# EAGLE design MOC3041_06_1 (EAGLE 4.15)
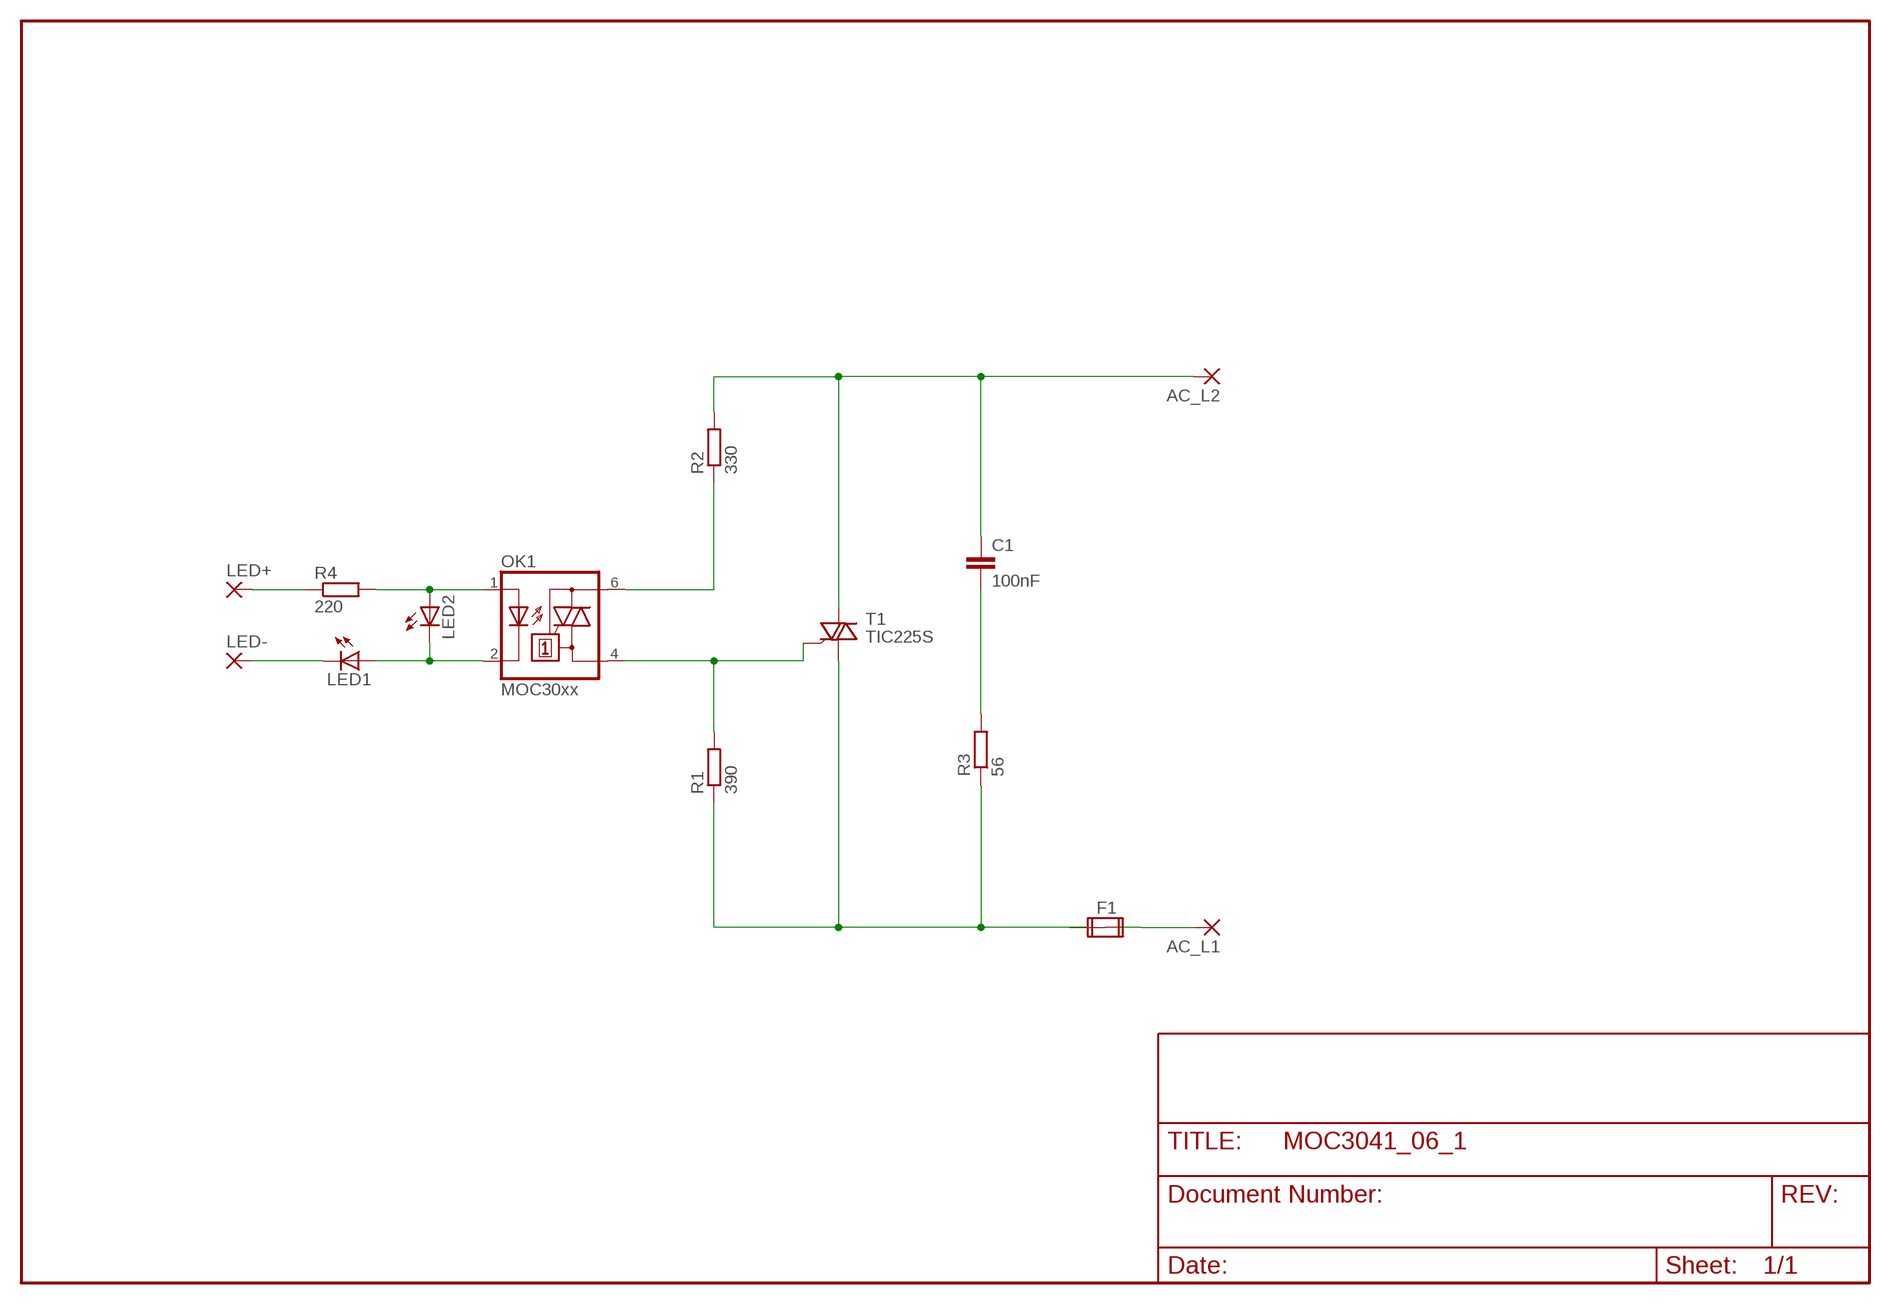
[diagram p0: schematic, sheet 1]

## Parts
AC_L1  3,17/1,1  [3,17/1,1]
AC_L2  3,17/1,1  [3,17/1,1]
C1  100nF  C-EU150-072X183  [C150-072X183]
F1  FUSE2P  [FUSE1]
LED1  LED3MM  [LED3MM]
LED2  LED3MM  [LED3MM]
LED+  3,17/1,1  [3,17/1,1]
LED-  3,17/1,1  [3,17/1,1]
OK1  MOC30xx  IL410  [DIL06]
R1  390  R-EU_0207/7  [0207/7]
R2  330  R-EU_0207/7  [0207/7]
R3  56  R-EU_0207/7  [0207/7]
R4  220  R-EU_0207/7  [0207/7]
T1  TIC225S  [TO220DS]

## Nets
N$1: AC_L2.1(P) C1.1 R2.2 T1.A2
N$2: C1.2 R3.2
N$4: OK1.4(A1) R1.2 T1.G
N$5: OK1.6(A2) R2.1
N$6: LED+.1(P) R4.1
N$7: LED2.A OK1.1(A) R4.2
N$8: LED1.A LED2.K(C) OK1.2(C)
N$9: LED1.K(C) LED-.1(P)
N$10: AC_L1.1(P) F1.2A F1.2B
N$11: F1.1A F1.1B R1.1 R3.1 T1.A1

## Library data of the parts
AC_L1 AC_L2 LED+ LED- = wirepad:3,17/1,1: THROUGH-HOLE PAD
C1 = rcl:C-EU: CAPACITOR, European symbol
F1 = special:FUSE2P: FUSE 5 x 20 mm
LED1 LED2 = led:LED: LED
OK1 = optocoupler:IL410: SIEMENS OPTO COUPLER
R1-R4 = rcl:R-EU_: RESISTOR, European symbol
T1 = triac:TIC225S: TRIAC

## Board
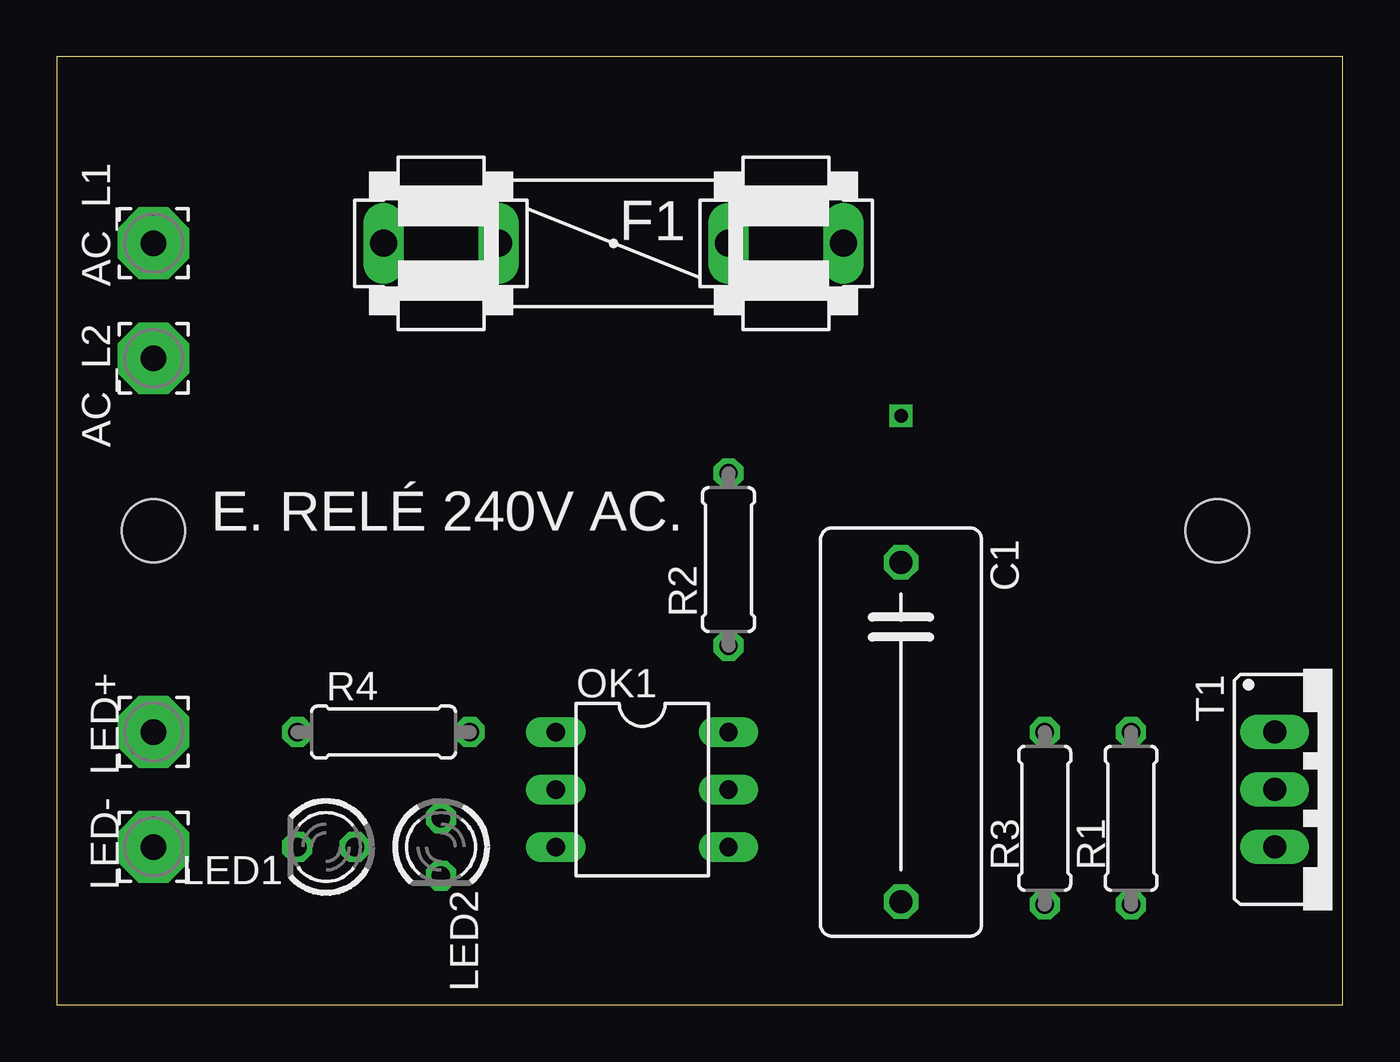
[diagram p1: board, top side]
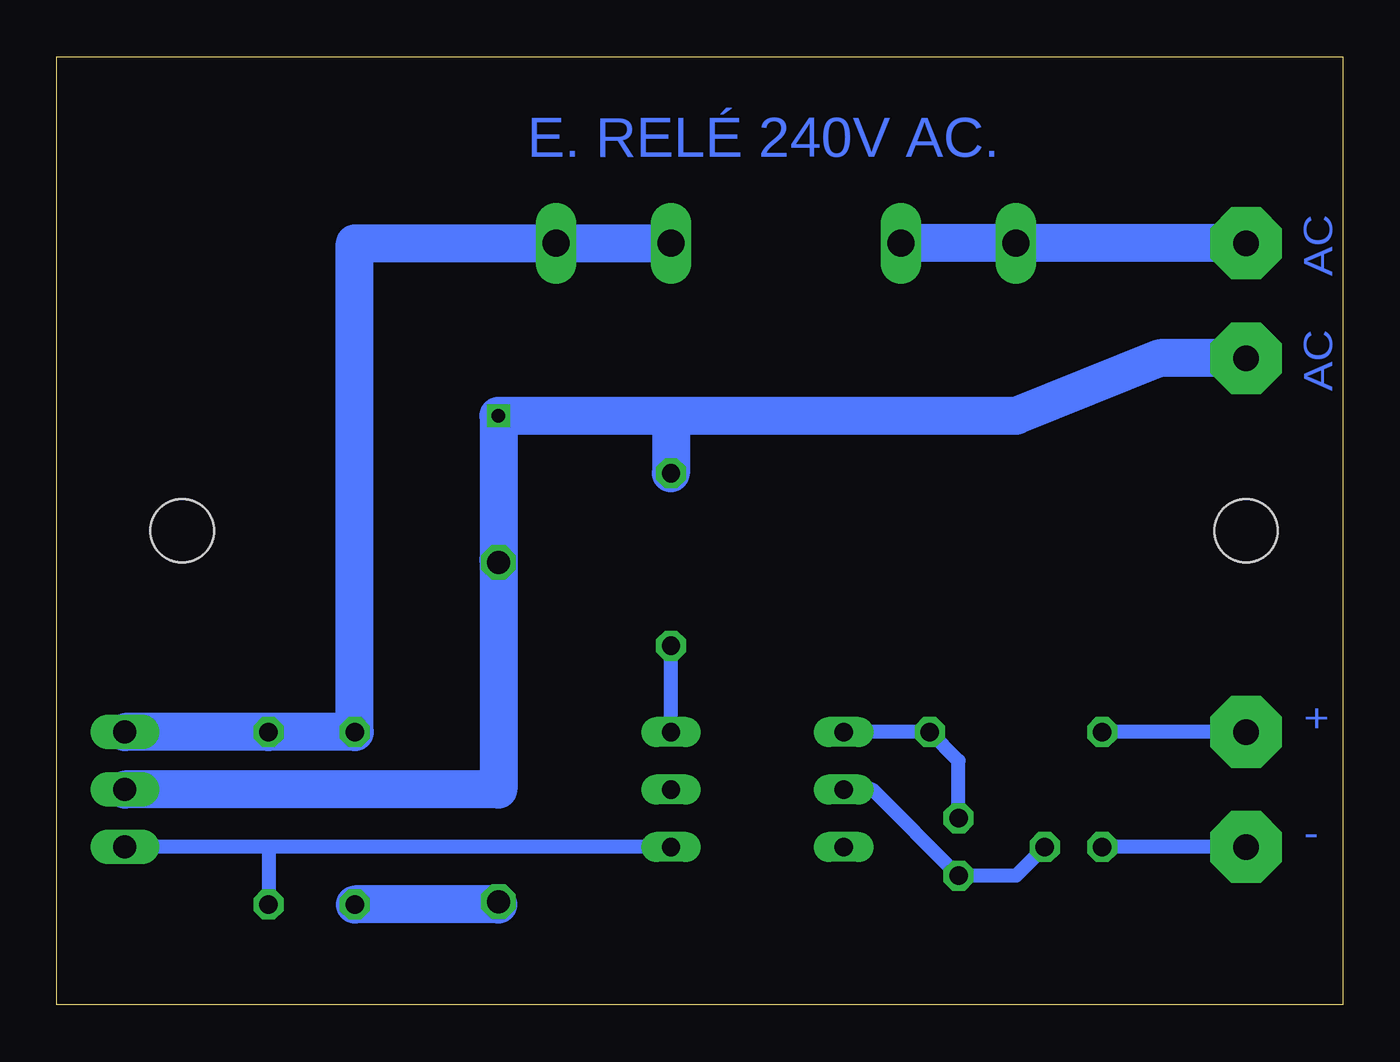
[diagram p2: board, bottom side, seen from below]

Size 56.82 x 41.9 mm. Coordinates in mm from the lower left corner, seen from the top.
Outline: 0,0 56.82,0 56.82,41.9 0,41.9 0,0
Copper layers (1*16): Top 0.035mm / dielectric 1.5mm / Bottom 0.035mm
Design rules "default": minimum track width 10mil, minimum drill 24mil, track to track 8mil, track to pad 8mil, pad to pad 8mil, via to via 8mil, smd to smd 8mil, copper to edge 40mil, drill to drill 8mil, minimum pad ring 10mil, minimum via ring 8mil, stop-mask expansion 4mil, vias tented up to drill 0mil, thermal gap 10mil
Holes 2.8 mm at 4.28,20.95 51.27,20.95

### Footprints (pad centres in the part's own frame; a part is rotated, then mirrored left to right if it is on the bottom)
3,17/1,1 = drill 1.118 pad 3.175 octagon: 1 0,0
C150-072X183 = drill 1.016 octagon: 1 -7.493,0; 2 7.493,0
FUSE1 = drill 1.194 long: 1A -10.16,0; 1B -5.08,0; 2A 10.16,0; 2B 5.08,0
LED3MM = drill 0.813 octagon: A -1.27,0; K 1.27,0
DIL06 = drill 0.813 long: 1 -2.54,-3.81; 2 0,-3.81; 3 2.54,-3.81; 4 2.54,3.81; 5 0,3.81; 6 -2.54,3.81
0207/7 = drill 0.813 octagon: 1 -3.81,0; 2 3.81,0
TO220DS = drill 1.016 long: A1 -2.54,-2.54; A2 0,-2.54; G 2.54,-2.54

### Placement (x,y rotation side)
AC_L1  4.28,33.65 90 top
AC_L2  4.28,28.57 270 top
C1  37.3,12.06 270 top
F1  24.6,33.65 180 top
LED1  11.9,6.98 180 top
LED2  16.98,6.98 270 top
LED+  4.28,12.06 0 top
LED-  4.28,6.98 0 top
OK1  25.87,9.52 270 top
R1  47.46,8.25 270 top
R2  29.68,19.68 90 top
R3  43.65,8.25 270 top
R4  14.44,12.06 0 top
T1  56.35,9.52 270 top

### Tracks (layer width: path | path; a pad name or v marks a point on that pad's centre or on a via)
N$1  (via drill 0.6)
  Bottom 0.254: 37.3,19.68 C1.1
  Bottom 1.676: T1.A2 37.3,9.52 37.3,19.68 v37.3,26.03 29.68,26.03 | 29.68,26.03 R2.2 | AC_L2.1 8.09,28.57 14.44,26.03 29.68,26.03
N$2
  Bottom 0.254: C1.2 37.3,4.44
  Bottom 1.676: 37.3,4.44 R3.2
N$4
  Bottom 0.61: 47.46,6.98 T1.G | 47.46,6.98 R1.2 | OK1.4 47.46,6.98
N$5
  Bottom 0.254: OK1.6 R2.1
  Bottom 0.61: OK1.6 R2.1
N$6
  Bottom 0.254: LED+.1 R4.1
  Bottom 0.61: LED+.1 R4.1
N$7
  Bottom 0.254: R4.2 OK1.1
  Bottom 0.61: OK1.1 R4.2 16.98,10.79 LED2.A
N$8
  Bottom 0.61: LED1.A 14.44,5.71 LED2.K 20.79,9.52 OK1.2
N$9
  Bottom 0.254: LED-.1 LED1.K
  Bottom 0.61: LED-.1 LED1.K
N$10
  Bottom 0.254: F1.2B F1.2A AC_L1.1
  Bottom 1.676: AC_L1.1 F1.2B
N$11
  Bottom 0.254: R1.1 T1.A1 | F1.1B F1.1A 43.65,33.65
  Bottom 1.676: T1.A1 R1.1 R3.1 43.65,33.65 F1.1B

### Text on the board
Bottom: E. RELÉ 240V AC. | AC | AC | + | -
tPlace: E. RELÉ 240V AC.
